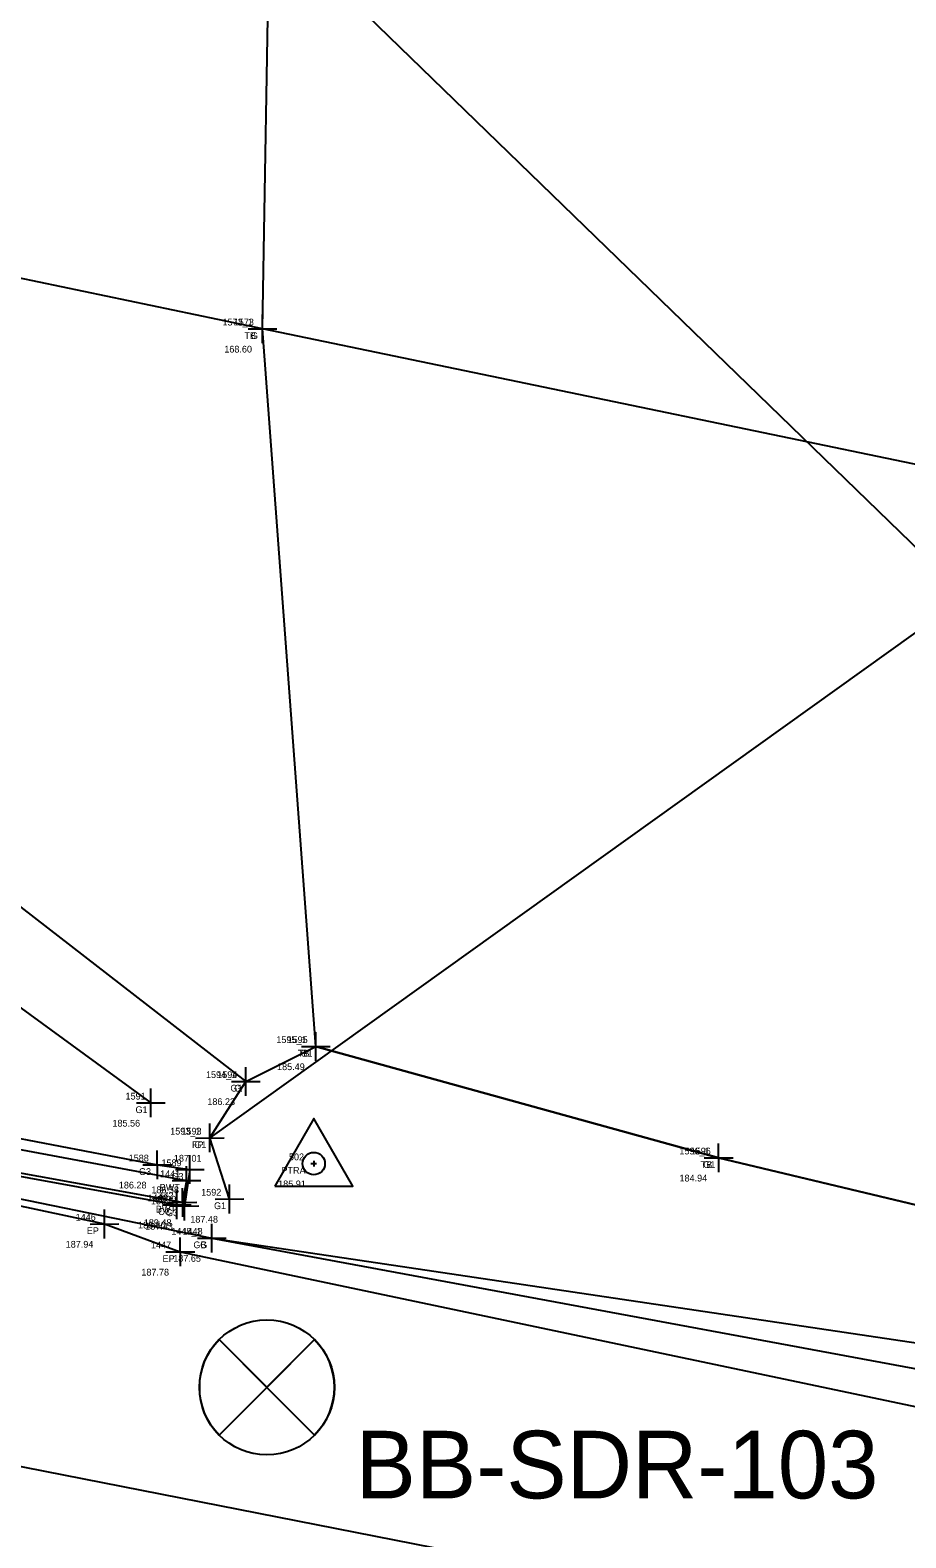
# Model space of a CAD drawing. Extents: x 1157913 to 1159198, y 600595 to 601244.
# Drawn here: x 1158727.6 to 1158766.4, y 600886 to 600952.9 of the extents above; entities that cross this region are included whole.
import ezdxf

# ---------------------------------------------------------------- set-up
doc = ezdxf.new("R2010")
doc.units = 0
for name, color, linetype in [('Default', 7, 'Continuous'), ('S_BoringLocation_AsDrilled', 7, 'Continuous'), ('S_Bridge_Wingwall', 7, 'Continuous'), ('S_Control_Traverse_Point', 7, 'Continuous'), ('S_Curb_Type_2', 7, 'Continuous'), ('S_Fencing_Page', 7, 'Continuous'), ('S_Field_Code', 7, 'Continuous'), ('S_Ground_Elevation', 7, 'Continuous'), ('S_Guardrail_Beam', 7, 'Continuous'), ('S_Point_Elevation', 7, 'Continuous'), ('S_Point_Name', 7, 'Continuous'), ('S_Roadway_Centerline', 7, 'Continuous'), ('S_Roadway_Edge_Pavement', 7, 'Continuous'), ('S_Survey_Shot', 7, 'Continuous'), ('S_Text', 7, 'Continuous'), ('S_Trees_Bush_Line', 7, 'Continuous'), ('S_Trees_TreeLine', 7, 'Continuous')]:
    doc.layers.add(name, color=color, linetype=linetype)

msp = doc.modelspace()

# ---------------------------------------------------------------- linework, layer by layer
at = {"layer": 'Default'}
msp.add_line((1158738.114, 600892.707), (1158738.114, 600892.707), dxfattribs=at)
at = {"layer": 'S_BoringLocation_AsDrilled'}
for p, q in [((1158735.997, 600894.825), (1158740.232, 600890.59)), ((1158735.997, 600890.59), (1158740.232, 600894.825))]:
    msp.add_line(p, q, dxfattribs=at)
for points in [[(1158735.997, 600890.59), (1158738.114, 600892.707), (1158735.997, 600894.825)], [(1158740.232, 600894.825), (1158738.114, 600892.707), (1158740.232, 600890.59)]]:
    msp.add_lwpolyline(points, dxfattribs=at)
msp.add_circle((1158738.114, 600892.707), 2.994, dxfattribs=at)
for start, end in [(135, 225), (315, 45)]:
    msp.add_arc((1158738.114, 600892.707), 2.994, start, end, dxfattribs=at)
at = {"layer": 'S_Bridge_Wingwall'}
msp.add_lwpolyline([(1158724.724, 600902.653), (1158724.864, 600903.69), (1158734.549, 600901.881), (1158734.38, 600900.915)], close=True, dxfattribs=at)
at = {"layer": 'S_Control_Traverse_Point'}
for p, q in [((1158740.066, 600902.633), (1158740.316, 600902.633)), ((1158740.191, 600902.758), (1158740.191, 600902.509))]:
    msp.add_line(p, q, dxfattribs=at)
msp.add_lwpolyline([(1158738.463, 600901.635), (1158741.92, 600901.635), (1158740.191, 600904.629)], close=True, dxfattribs=at)
msp.add_circle((1158740.191, 600902.633), 0.499, dxfattribs=at)
at = {"layer": 'S_Curb_Type_2'}
msp.add_lwpolyline([(1158725.365, 600902.406), (1158734.123, 600900.806)], dxfattribs=at)
at = {"layer": 'S_Fencing_Page'}
msp.add_lwpolyline([(1158780.165, 600969.797), (1158774.944, 600931.981), (1158735.583, 600903.772)], dxfattribs=at)
at = {"layer": 'S_Ground_Elevation'}
for points in [[(1159148.387, 600827.64), (1159092.305, 600843.388), (1159023.639, 600857.423), (1158956.467, 600873.915), (1158901.674, 600888.215), (1158826.796, 600914.424), (1158787.654, 600925.882), (1158774.944, 600931.981), (1158737.918, 600939.668), (1158712.165, 600945.049), (1158701.311, 600943.229)], [(1158703.769, 600939.439), (1158713.512, 600926.246), (1158726.146, 600914.827), (1158737.183, 600906.281)], [(1158697.641, 600935.742), (1158709.272, 600923.047), (1158724.634, 600911.404), (1158732.975, 600905.326)], [(1158692.85, 600914.562), (1158706.956, 600910.503), (1158722.22, 600905.407), (1158724.615, 600904.235), (1158733.258, 600902.581), (1158734.697, 600902.369), (1158734.457, 600900.754)], [(1158736.457, 600901.064), (1158735.583, 600903.772), (1158737.183, 600906.281), (1158740.287, 600907.832), (1158758.145, 600902.891), (1158800.381, 600892.803)], [(1158735.673, 600899.33), (1158779.346, 600891.222), (1158821.057, 600885.008), (1158872.579, 600874.816), (1158921.179, 600864.906), (1158974.289, 600854.576), (1159026.528, 600844.124), (1159039.988, 600841.695), (1159053.262, 600839.632), (1159065.358, 600838.096), (1159078.578, 600837.332), (1159119.614, 600826.577), (1159142.711, 600822.91)]]:
    msp.add_lwpolyline(points, dxfattribs=at)
at = {"layer": 'S_Guardrail_Beam'}
msp.add_lwpolyline([(1158723.142, 600901.903), (1158735.673, 600899.33), (1158779.708, 600892.778), (1158821.057, 600885.008), (1158872.579, 600874.816), (1158921.179, 600864.906), (1158974.289, 600854.576), (1159026.528, 600844.124), (1159039.988, 600841.695), (1159053.262, 600839.632), (1159065.358, 600838.096), (1159078.578, 600837.332)], dxfattribs=at)
at = {"layer": 'S_Roadway_Centerline'}
msp.add_lwpolyline([(1158721.055, 600890.395), (1158723.064, 600890.013), (1158776.46, 600879.509), (1158819.528, 600871.149), (1158868.15, 600861.085), (1158918.713, 600851.111), (1158970.46, 600840.7), (1159022.781, 600830.456), (1159075.358, 600819.935), (1159137.497, 600807.122), (1159188.145, 600796.962)], dxfattribs=at)
at = {"layer": 'S_Roadway_Edge_Pavement'}
msp.add_lwpolyline([(1158723.29, 600901.545), (1158725.228, 600901.176), (1158730.919, 600899.955), (1158734.277, 600898.718), (1158779.347, 600889.226), (1158821.037, 600881.144), (1158871.084, 600871.138), (1158921.105, 600861.196), (1158972.945, 600850.848), (1159025.625, 600840.648), (1159077.094, 600830.514), (1159119.992, 600821.415), (1159145.866, 600816.084), (1159193.179, 600806.656)], dxfattribs=at)
at = {"layer": 'S_Survey_Shot'}
for p, q in [((1158737.919, 600939.032), (1158737.916, 600940.305)), ((1158737.919, 600939.032), (1158737.916, 600940.305)), ((1158737.282, 600939.667), (1158738.554, 600939.67)), ((1158737.282, 600939.667), (1158738.554, 600939.67)), ((1158737.918, 600939.668), (1158737.918, 600939.668)), ((1158737.918, 600939.668), (1158737.918, 600939.668)), ((1158740.289, 600907.196), (1158740.286, 600908.468)), ((1158740.289, 600907.196), (1158740.286, 600908.468)), ((1158739.651, 600907.831), (1158740.924, 600907.833)), ((1158739.651, 600907.831), (1158740.924, 600907.833)), ((1158740.287, 600907.832), (1158740.287, 600907.832)), ((1158740.287, 600907.832), (1158740.287, 600907.832)), ((1158737.184, 600905.645), (1158737.182, 600906.918)), ((1158737.184, 600905.645), (1158737.182, 600906.918)), ((1158732.976, 600904.689), (1158732.973, 600905.962)), ((1158736.547, 600906.28), (1158737.819, 600906.283)), ((1158736.547, 600906.28), (1158737.819, 600906.283)), ((1158737.183, 600906.281), (1158737.183, 600906.281)), ((1158737.183, 600906.281), (1158737.183, 600906.281)), ((1158732.339, 600905.324), (1158733.611, 600905.327)), ((1158732.975, 600905.326), (1158732.975, 600905.326)), ((1158735.584, 600903.136), (1158735.582, 600904.408)), ((1158735.584, 600903.136), (1158735.582, 600904.408)), ((1158734.947, 600903.77), (1158736.219, 600903.773)), ((1158734.947, 600903.77), (1158736.219, 600903.773)), ((1158735.583, 600903.772), (1158735.583, 600903.772)), ((1158735.583, 600903.772), (1158735.583, 600903.772)), ((1158758.147, 600902.254), (1158758.144, 600903.527)), ((1158758.147, 600902.254), (1158758.144, 600903.527)), ((1158733.26, 600901.944), (1158733.257, 600903.217)), ((1158734.699, 600901.732), (1158734.696, 600903.005)), ((1158757.509, 600902.889), (1158758.781, 600902.892)), ((1158757.509, 600902.889), (1158758.781, 600902.892)), ((1158758.145, 600902.891), (1158758.145, 600902.891)), ((1158758.145, 600902.891), (1158758.145, 600902.891)), ((1158732.622, 600902.579), (1158733.895, 600902.582)), ((1158733.258, 600902.581), (1158733.258, 600902.581)), ((1158734.061, 600902.367), (1158735.334, 600902.37)), ((1158734.551, 600901.245), (1158734.548, 600902.517)), ((1158734.697, 600902.369), (1158734.697, 600902.369)), ((1158733.913, 600901.88), (1158735.186, 600901.882)), ((1158734.125, 600900.17), (1158734.122, 600901.442)), ((1158734.381, 600900.279), (1158734.379, 600901.552)), ((1158734.458, 600900.117), (1158734.456, 600901.39)), ((1158734.549, 600901.881), (1158734.549, 600901.881)), ((1158736.458, 600900.428), (1158736.456, 600901.701)), ((1158733.487, 600900.804), (1158734.76, 600900.807)), ((1158733.744, 600900.914), (1158735.016, 600900.917)), ((1158733.821, 600900.752), (1158735.093, 600900.755)), ((1158734.123, 600900.806), (1158734.123, 600900.806)), ((1158734.38, 600900.915), (1158734.38, 600900.915)), ((1158734.457, 600900.754), (1158734.457, 600900.754)), ((1158735.821, 600901.063), (1158737.093, 600901.066)), ((1158736.457, 600901.064), (1158736.457, 600901.064)), ((1158730.282, 600899.953), (1158731.555, 600899.956)), ((1158730.92, 600899.318), (1158730.917, 600900.591)), ((1158730.919, 600899.955), (1158730.919, 600899.955)), ((1158735.674, 600898.694), (1158735.671, 600899.966)), ((1158735.674, 600898.694), (1158735.671, 600899.966)), ((1158734.278, 600898.082), (1158734.275, 600899.354)), ((1158735.036, 600899.329), (1158736.309, 600899.331)), ((1158735.036, 600899.329), (1158736.309, 600899.331)), ((1158735.673, 600899.33), (1158735.673, 600899.33)), ((1158735.673, 600899.33), (1158735.673, 600899.33)), ((1158733.641, 600898.717), (1158734.913, 600898.719)), ((1158734.277, 600898.718), (1158734.277, 600898.718))]:
    msp.add_line(p, q, dxfattribs=at)
at = {"layer": 'S_Trees_Bush_Line'}
msp.add_lwpolyline([(1158850.822, 600882.594), (1158835.907, 600886.226), (1158800.381, 600892.803), (1158758.145, 600902.891), (1158740.287, 600907.832), (1158737.918, 600939.668), (1158738.238, 600957.783)], dxfattribs=at)
at = {"layer": 'S_Trees_TreeLine'}
msp.add_lwpolyline([(1158771.003, 600925.976), (1158738.238, 600957.783), (1158741.008, 600986.267), (1158744.273, 601015.539), (1158747.504, 601038.645), (1158754.157, 601082.26), (1158768.91, 601136.819), (1158778.165, 601197.117)], dxfattribs=at)

# ---------------------------------------------------------------- texts
at = {"layer": 'S_Field_Code'}
for s, p in [('TB', (1158737.117, 600939.218)), ('G', (1158737.403, 600939.218)), ('TB', (1158739.487, 600907.382)), ('G1', (1158739.603, 600907.382)), ('G1', (1158736.498, 600905.831)), ('G', (1158736.668, 600905.831)), ('G1', (1158732.29, 600904.876)), ('FP', (1158734.796, 600903.322)), ('G1', (1158734.898, 600903.322)), ('TB', (1158757.344, 600902.441)), ('G1', (1158757.46, 600902.441)), ('G3', (1158732.443, 600902.131)), ('G3', (1158733.882, 600901.919)), ('PTRA', (1158738.76, 600902.183)), ('BWT', (1158733.364, 600901.431)), ('BWT', (1158733.194, 600900.465)), ('CC', (1158733.294, 600900.356)), ('G3', (1158733.642, 600900.304)), ('G1', (1158735.772, 600900.614)), ('EP', (1158730.132, 600899.505)), ('GB', (1158734.858, 600898.88)), ('G', (1158735.158, 600898.88)), ('EP', (1158733.49, 600898.268))]:
    msp.add_text(s, height=0.3, dxfattribs=at).set_placement(p)
at = {"layer": 'S_Point_Elevation'}
for s, p in [('168.60', (1158736.227, 600938.618)), ('168.60', (1158736.227, 600938.618)), ('185.49', (1158738.566, 600906.782)), ('185.49', (1158738.566, 600906.782)), ('186.23', (1158735.475, 600905.231)), ('186.23', (1158735.475, 600905.231)), ('185.56', (1158731.267, 600904.276)), ('187.01', (1158733.991, 600902.722)), ('187.01', (1158733.991, 600902.722)), ('184.94', (1158756.409, 600901.841)), ('184.94', (1158756.409, 600901.841)), ('186.28', (1158731.551, 600901.531)), ('186.58', (1158732.99, 600901.319)), ('185.91', (1158738.614, 600901.583)), ('189.51', (1158732.972, 600900.831)), ('188.50', (1158732.404, 600899.756)), ('189.48', (1158732.658, 600899.865)), ('187.43', (1158732.719, 600899.704)), ('187.48', (1158734.719, 600900.014)), ('187.94', (1158729.195, 600898.905)), ('187.78', (1158732.55, 600897.668)), ('187.65', (1158733.963, 600898.28)), ('187.65', (1158733.963, 600898.28))]:
    msp.add_text(s, height=0.3, dxfattribs=at).set_placement(p)
at = {"layer": 'S_Point_Name'}
for s, p in [('1573_1', (1158736.146, 600939.818)), ('1573', (1158736.645, 600939.818)), ('1595_1', (1158738.533, 600907.982)), ('1595', (1158739.031, 600907.982)), ('1594_1', (1158735.414, 600906.431)), ('1594', (1158735.912, 600906.431)), ('1591', (1158731.848, 600905.476)), ('1593_1', (1158733.828, 600903.922)), ('1593', (1158734.326, 600903.922)), ('1596_1', (1158756.405, 600903.041)), ('1596', (1158756.903, 600903.041)), ('1588', (1158731.987, 600902.731)), ('1589', (1158733.441, 600902.519)), ('502', (1158739.093, 600902.783)), ('1441', (1158733.38, 600902.031)), ('1442', (1158733.081, 600901.065)), ('1592', (1158735.201, 600901.214)), ('1443', (1158732.824, 600900.956)), ('1590', (1158733.203, 600900.904)), ('1446', (1158729.634, 600900.105)), ('1448_1', (1158733.875, 600899.48)), ('1448', (1158734.374, 600899.48)), ('1447', (1158732.975, 600898.868))]:
    msp.add_text(s, height=0.3, dxfattribs=at).set_placement(p)
at = {"layer": 'S_Text'}
msp.add_text('BB-SDR-103', height=3, dxfattribs=at).set_placement((1158742.043, 600887.781))

doc.saveas('drawing.dxf')
